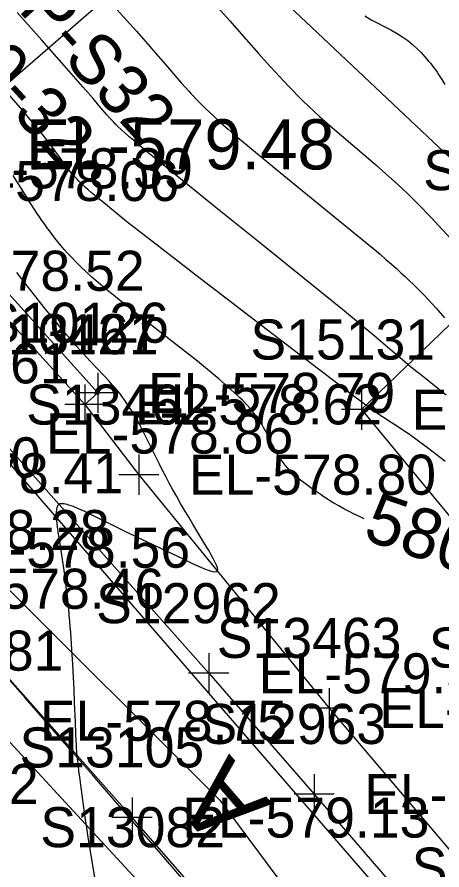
# Model space of a CAD drawing. Extents: x 1729869 to 1735532, y 648588 to 653771.
# Drawn here: x 1731271.9 to 1731314.3, y 651970.4 to 652055.5 of the extents above; entities that cross this region are included whole.
import ezdxf

# ---------------------------------------------------------------- set-up
doc = ezdxf.new("R2010")
doc.units = 0
for name, color, linetype in [('SURVEY - CENTERLINE - Preliminary', 7, 'Continuous'), ('SURVEY - CENTERLINE - Preliminary Text', 7, 'Continuous'), ('SURVEY - CONTOURS - Index with Text', 7, 'Continuous'), ('SURVEY - CONTOURS - Intermediate with optional Text', 7, 'Continuous'), ('SURVEY - CONTROL - Points - Elevations', 7, 'Continuous'), ('SURVEY - CONTROL with Text', 7, 'Continuous'), ('SURVEY - DRAINAGE - Area Shapes', 7, 'Continuous'), ('SURVEY - DRAINAGE - Area Shapes Text', 7, 'Continuous'), ('SURVEY - DRAINAGE - Storm Sewer - Points - Numbers', 7, 'Continuous'), ('SURVEY - DTM - Breaklines', 7, 'Continuous'), ('SURVEY - DTM - Breaklines - Points - Elevations', 7, 'Continuous'), ('SURVEY - DTM - Breaklines - Points - Locators', 7, 'Continuous'), ('SURVEY - DTM - Breaklines - Points - Numbers', 7, 'Continuous'), ('SURVEY - ROADSIDE BARRIERS - Points - Elevations', 7, 'Continuous'), ('SURVEY - TRANSPORTATION - Features', 7, 'Continuous'), ('SURVEY - TRANSPORTATION - Features - Points - Elevations', 7, 'Continuous'), ('SURVEY - TRANSPORTATION - Features - Points - Locators', 7, 'Continuous'), ('SURVEY - TRANSPORTATION - Features - Points - Numbers', 7, 'Continuous'), ('SURVEY - TRANSPORTATION - Roads', 7, 'Continuous'), ('SURVEY - TRANSPORTATION - Roads - Points - Elevations', 7, 'Continuous'), ('SURVEY - TRANSPORTATION - Roads - Points - Locators', 7, 'Continuous'), ('SURVEY - TRANSPORTATION - Roads - Points - Numbers', 7, 'Continuous')]:
    doc.layers.add(name, color=color, linetype=linetype)

msp = doc.modelspace()

# ---------------------------------------------------------------- linework, layer by layer
at = {"layer": 'SURVEY - CENTERLINE - Preliminary'}
msp.add_arc((1729018.342, 650008.232), 3000, 36.727042, 45.05905, dxfattribs=at)
at = {"layer": 'SURVEY - CENTERLINE - Preliminary Text'}
for p, q in [((1731256.757, 652012.701), (1731292.149, 651977.382)), ((1731292.149, 651977.382), (1731322.049, 651937.307))]:
    msp.add_line(p, q, dxfattribs=at)
at = {"layer": 'SURVEY - CONTOURS - Index with Text'}
for points in [[(1731306.619, 652055.655), (1731307.262, 652055.276), (1731307.917, 652054.924), (1731308.573, 652054.586), (1731309.22, 652054.25), (1731309.845, 652053.906), (1731310.437, 652053.54), (1731310.936, 652053.184), (1731311.403, 652052.805), (1731311.839, 652052.408), (1731312.249, 652051.995), (1731312.635, 652051.571), (1731313.001, 652051.14), (1731313.177, 652050.924), (1731313.348, 652050.706), (1731313.515, 652050.486), (1731313.679, 652050.263), (1731313.839, 652050.037), (1731313.996, 652049.808), (1731314.31, 652049.322), (1731314.611, 652048.82)], [(1731306.58, 652005.464), (1731306.117, 652005.678), (1731305.584, 652005.932), (1731305.056, 652006.193), (1731304.537, 652006.462), (1731304.029, 652006.74), (1731303.536, 652007.027), (1731303.211, 652007.227), (1731302.892, 652007.431), (1731302.579, 652007.637), (1731302.27, 652007.846), (1731301.66, 652008.268), (1731301.256, 652008.551), (1731300.856, 652008.836), (1731300.466, 652009.123), (1731300.089, 652009.416), (1731299.729, 652009.716), (1731299.391, 652010.025), (1731299.136, 652010.28), (1731298.897, 652010.541), (1731298.673, 652010.808), (1731298.463, 652011.079), (1731298.267, 652011.355), (1731298.083, 652011.634), (1731297.917, 652011.906), (1731297.761, 652012.18), (1731297.612, 652012.457), (1731297.467, 652012.737), (1731297.326, 652013.02), (1731296.943, 652013.799), (1731296.815, 652014.051), (1731296.678, 652014.309), (1731296.531, 652014.574), (1731296.37, 652014.846), (1731296.143, 652015.204), (1731295.884, 652015.578), (1731295.588, 652015.972), (1731295.248, 652016.387), (1731294.857, 652016.828), (1731294.41, 652017.296), (1731294.164, 652017.542), (1731293.901, 652017.795), (1731292.097, 652019.399), (1731289.918, 652021.182), (1731287.527, 652023.063), (1731285.086, 652024.956), (1731282.756, 652026.779), (1731280.698, 652028.448), (1731280.009, 652029.035), (1731279.38, 652029.589), (1731278.806, 652030.112), (1731278.283, 652030.608), (1731277.806, 652031.079), (1731277.37, 652031.527), (1731276.979, 652031.945), (1731276.619, 652032.347), (1731276.286, 652032.735), (1731275.975, 652033.111), (1731275.682, 652033.479), (1731275.403, 652033.841), (1731275.14, 652034.191), (1731274.885, 652034.541), (1731274.635, 652034.891), (1731274.388, 652035.244), (1731274.143, 652035.602), (1731273.898, 652035.967), (1731273.657, 652036.333), (1731273.412, 652036.709), (1731273.162, 652037.097), (1731272.907, 652037.499), (1731272.374, 652038.348), (1731271.959, 652039.016), (1731271.52, 652039.719)]]:
    msp.add_lwpolyline(points, dxfattribs=at)
at = {"layer": 'SURVEY - CONTOURS - Intermediate with optional Text'}
for points in [[(1731280.868, 652057.433), (1731283.821, 652054.117), (1731285.173, 652052.593), (1731286.009, 652051.642), (1731286.747, 652050.795), (1731288.31, 652048.983), (1731288.77, 652048.461), (1731289.012, 652048.191), (1731289.26, 652047.919), (1731289.522, 652047.637), (1731289.801, 652047.344), (1731290.1, 652047.036), (1731290.422, 652046.712), (1731290.772, 652046.369), (1731291.146, 652046.011), (1731291.552, 652045.631), (1731291.995, 652045.226), (1731292.476, 652044.794), (1731292.999, 652044.333), (1731293.567, 652043.841), (1731295.704, 652042.044), (1731298.18, 652040.014), (1731303.483, 652035.715), (1731305.98, 652033.674), (1731308.152, 652031.858), (1731308.739, 652031.354), (1731309.282, 652030.881), (1731309.783, 652030.437), (1731310.244, 652030.02), (1731310.67, 652029.628), (1731311.063, 652029.259), (1731311.498, 652028.841), (1731311.894, 652028.45), (1731312.255, 652028.084), (1731312.585, 652027.742), (1731312.89, 652027.419), (1731313.324, 652026.947), (1731313.753, 652026.469), (1731314.582, 652025.531)], [(1731291.393, 652057.137), (1731293.123, 652055.19), (1731294.796, 652053.296), (1731296.026, 652051.902), (1731296.845, 652050.982), (1731297.257, 652050.523), (1731297.676, 652050.062), (1731298.104, 652049.597), (1731298.544, 652049.126), (1731298.999, 652048.649), (1731299.462, 652048.171), (1731299.945, 652047.685), (1731300.448, 652047.189), (1731300.976, 652046.681), (1731301.53, 652046.161), (1731302.114, 652045.627), (1731303.171, 652044.688), (1731304.289, 652043.721), (1731305.435, 652042.743), (1731306.578, 652041.771), (1731307.688, 652040.819), (1731308.732, 652039.906), (1731309.326, 652039.373), (1731309.885, 652038.86), (1731310.413, 652038.365), (1731310.91, 652037.889), (1731311.379, 652037.431), (1731311.822, 652036.991), (1731312.346, 652036.46), (1731312.84, 652035.948), (1731313.313, 652035.451), (1731313.979, 652034.742), (1731315.248, 652033.374)], [(1731314.739, 652017.786), (1731313.907, 652018.482), (1731313.381, 652018.911), (1731312.891, 652019.302), (1731312.177, 652019.861), (1731311.685, 652020.245), (1731311.443, 652020.438), (1731311.199, 652020.634), (1731310.952, 652020.836), (1731310.701, 652021.047), (1731310.162, 652021.511), (1731309.175, 652022.366), (1731308.432, 652023), (1731307.548, 652023.743), (1731304.39, 652026.34), (1731300.441, 652029.539), (1731296.105, 652033.029), (1731291.786, 652036.502), (1731287.888, 652039.648), (1731284.816, 652042.159), (1731284.143, 652042.719), (1731283.564, 652043.206), (1731283.072, 652043.627), (1731282.654, 652043.993), (1731282.306, 652044.306), (1731282.017, 652044.575), (1731281.77, 652044.814), (1731281.556, 652045.031), (1731281.364, 652045.236), (1731281.177, 652045.445), (1731280.884, 652045.785), (1731280.089, 652046.72), (1731279.505, 652047.398), (1731278.758, 652048.259), (1731278.47, 652048.589), (1731276.616, 652050.699), (1731274.368, 652053.239), (1731271.923, 652055.987)], [(1731314.64, 652011.174), (1731314.198, 652011.53), (1731313.76, 652011.878), (1731313.328, 652012.216), (1731312.902, 652012.543), (1731312.507, 652012.84), (1731312.117, 652013.126), (1731311.733, 652013.403), (1731311.353, 652013.67), (1731310.977, 652013.929), (1731310.421, 652014.305), (1731309.68, 652014.795), (1731309.091, 652015.182), (1731308.674, 652015.458), (1731308.236, 652015.753), (1731307.772, 652016.07), (1731307.278, 652016.416), (1731306.748, 652016.795), (1731305.92, 652017.406), (1731304.999, 652018.101), (1731303.976, 652018.884), (1731300.182, 652021.806), (1731296.93, 652024.294), (1731293.324, 652027.046), (1731289.614, 652029.884), (1731286.051, 652032.631), (1731282.885, 652035.111), (1731280.366, 652037.147), (1731279.985, 652037.466), (1731279.634, 652037.763), (1731279.313, 652038.041), (1731279.018, 652038.301), (1731278.749, 652038.543), (1731278.504, 652038.768), (1731278.287, 652038.974), (1731278.089, 652039.167), (1731277.909, 652039.348), (1731277.745, 652039.52), (1731277.594, 652039.685), (1731277.454, 652039.843), (1731277.327, 652039.993), (1731277.206, 652040.14), (1731277.09, 652040.286), (1731276.978, 652040.433), (1731276.754, 652040.736), (1731276.139, 652041.595), (1731275.755, 652042.121), (1731275.49, 652042.476), (1731275.195, 652042.865), (1731274.866, 652043.289), (1731274.5, 652043.751), (1731274.095, 652044.253), (1731272.439, 652046.232), (1731270.447, 652048.531)], [(1731279.697, 651969.507), (1731279.481, 651970.85), (1731279.015, 651973.689), (1731278.869, 651974.619), (1731278.831, 651974.867), (1731278.749, 651975.423), (1731278.576, 651976.636), (1731278.399, 651977.928), (1731278.235, 651979.152), (1731278.162, 651979.715), (1731278.093, 651980.267), (1731278.028, 651980.803), (1731277.97, 651981.321), (1731277.921, 651981.817), (1731277.886, 651982.203), (1731277.858, 651982.575), (1731277.833, 651982.938), (1731277.812, 651983.293), (1731277.778, 651983.999), (1731277.729, 651985.203), (1731277.655, 651987.131), (1731277.597, 651988.49), (1731277.544, 651989.629), (1731277.471, 651990.987), (1731277.418, 651991.891), (1731277.349, 651992.996), (1731277.311, 651993.553), (1731277.271, 651994.113), (1731277.227, 651994.677), (1731277.181, 651995.245), (1731277.127, 651995.859), (1731277.068, 651996.479), (1731277.005, 651997.103), (1731276.936, 651997.733), (1731276.862, 651998.368), (1731276.783, 651999.007), (1731276.727, 651999.436), (1731276.668, 651999.867), (1731276.544, 652000.738), (1731276.411, 652001.619), (1731276.168, 652003.184), (1731276.056, 652003.936), (1731275.962, 652004.643), (1731275.894, 652005.287), (1731275.858, 652005.849), (1731275.855, 652006.024), (1731275.857, 652006.186), (1731275.866, 652006.335), (1731275.88, 652006.464), (1731275.902, 652006.581), (1731275.932, 652006.683), (1731275.97, 652006.772), (1731276.018, 652006.846), (1731276.077, 652006.906), (1731276.143, 652006.948), (1731276.219, 652006.978), (1731276.306, 652006.995), (1731276.402, 652007), (1731276.507, 652006.994), (1731276.622, 652006.979), (1731276.753, 652006.952), (1731276.895, 652006.916), (1731277.046, 652006.871), (1731277.499, 652006.709), (1731278.008, 652006.498), (1731278.563, 652006.248), (1731279.151, 652005.968), (1731279.761, 652005.669), (1731281.593, 652004.763), (1731282.804, 652004.171), (1731283.779, 652003.702), (1731288.572, 652001.419), (1731289.363, 652001.045), (1731289.862, 652000.814), (1731290.101, 652000.706), (1731290.333, 652000.603), (1731290.555, 652000.508), (1731290.881, 652000.377), (1731291.177, 652000.272), (1731291.434, 652000.2), (1731291.647, 652000.169), (1731291.807, 652000.185), (1731291.907, 652000.256), (1731291.941, 652000.391), (1731291.913, 652000.583), (1731291.831, 652000.827), (1731291.702, 652001.115), (1731291.534, 652001.442), (1731291.336, 652001.801), (1731291.075, 652002.252), (1731290.665, 652002.943), (1731289.472, 652004.92), (1731289.053, 652005.618), (1731288.636, 652006.323), (1731288.242, 652007.002), (1731287.856, 652007.68), (1731287.479, 652008.355), (1731287.112, 652009.027), (1731286.756, 652009.694), (1731286.413, 652010.354), (1731286.134, 652010.903), (1731285.862, 652011.448), (1731285.068, 652013.054), (1731284.805, 652013.582), (1731284.467, 652014.246), (1731284.121, 652014.902), (1731283.766, 652015.546), (1731283.399, 652016.173), (1731283.016, 652016.78), (1731282.616, 652017.363), (1731282.409, 652017.645), (1731282.196, 652017.921), (1731281.831, 652018.365), (1731281.452, 652018.8), (1731281.061, 652019.229), (1731280.66, 652019.657), (1731279.834, 652020.527), (1731279.33, 652021.065), (1731278.821, 652021.62), (1731278.308, 652022.189), (1731277.792, 652022.771), (1731277.275, 652023.365), (1731276.758, 652023.968), (1731276.255, 652024.566), (1731275.754, 652025.17), (1731275.255, 652025.78), (1731274.759, 652026.393), (1731274.265, 652027.01), (1731273.774, 652027.628), (1731273.298, 652028.232), (1731272.826, 652028.836), (1731272.358, 652029.439), (1731271.895, 652030.041)]]:
    msp.add_lwpolyline(points, dxfattribs=at)
at = {"layer": 'SURVEY - DRAINAGE - Area Shapes'}
for points in [[(1731097.142, 652171.409), (1731011.148, 652256.97), (1730865.03, 652403.158), (1730749.606, 652518.939), (1730781.764, 652550.883), (1730851.291, 652571.58), (1730949.072, 652515.98), (1730982.838, 652438.563), (1731020.351, 652368.14), (1731165.291, 652192.393), (1731281.807, 652137.032), (1731316.797, 652088.672), (1731252.279, 652032.718), (1731179.777, 652109.245)], [(1731447.67, 651794.75), (1731494.62, 651848.132), (1731494.044, 651850.166), (1731316.797, 652088.672), (1731252.279, 652032.718), (1731331.927, 651940.868), (1731377.361, 651886.729)]]:
    msp.add_lwpolyline(points, close=True, dxfattribs=at)
at = {"layer": 'SURVEY - DRAINAGE - Area Shapes Text'}
msp.add_lwpolyline([(1731252.279, 652032.718), (1731252.279, 652032.718), (1731331.927, 651940.868), (1731382.756, 651879.672), (1731447.67, 651794.75), (1731482.093, 651747.619), (1731463.009, 651708.574), (1731417.334, 651769.604), (1731372.727, 651826.43), (1731331.142, 651879.707), (1731270.184, 651948.802), (1731219.221, 652002.428), (1731149.8, 652071.308), (1731071.45, 652144.137), (1731094.843, 652173.647), (1731097.142, 652171.409), (1731179.777, 652109.245)], close=True, dxfattribs=at)
at = {"layer": 'SURVEY - DTM - Breaklines'}
for points in [[(1731035.462, 652269.556), (1731036.254, 652268.75), (1731049.78, 652255.258), (1731071.01, 652234.055), (1731092.233, 652212.831), (1731113.392, 652191.515), (1731134.61, 652170.281), (1731155.653, 652148.89), (1731176.704, 652127.515), (1731197.722, 652105.922), (1731218.638, 652084.352), (1731239.234, 652062.543), (1731259.779, 652040.444), (1731279.977, 652018.028), (1731278.681, 652016.879)], [(1731173.177, 652162.133), (1731185.96, 652157.822), (1731193.021, 652156.379), (1731200.301, 652157.188), (1731222.402, 652143.758), (1731259.134, 652109.719), (1731287.468, 652067.609), (1731323.876, 652033.257), (1731358.72, 651988.1), (1731387.259, 651947.011), (1731417.761, 651907.382), (1731444.904, 651865.257), (1731475.096, 651825.397), (1731506.912, 651797.592), (1731507.786, 651795.548)], [(1731323.876, 652033.257), (1731306.29, 652016.355), (1731329.689, 651988.026)]]:
    msp.add_lwpolyline(points, dxfattribs=at)
at = {"layer": 'SURVEY - DTM - Breaklines - Points - Locators'}
for p, q in [((1731279.977, 652020.028), (1731279.977, 652016.028)), ((1731278.681, 652018.879), (1731278.681, 652014.879)), ((1731306.29, 652018.355), (1731306.29, 652014.355)), ((1731281.977, 652018.028), (1731277.977, 652018.028)), ((1731280.681, 652016.879), (1731276.681, 652016.879)), ((1731308.29, 652016.355), (1731304.29, 652016.355))]:
    msp.add_line(p, q, dxfattribs=at)
at = {"layer": 'SURVEY - TRANSPORTATION - Features'}
msp.add_lwpolyline([(1731258.402, 652039.18), (1731278.681, 652016.879), (1731284.056, 652009.864), (1731303.088, 651986.573), (1731322.547, 651963.645), (1731341.9, 651940.638), (1731361.109, 651917.48), (1731380.078, 651894.112), (1731398.716, 651870.573), (1731417.161, 651846.862), (1731435.465, 651822.971), (1731453.412, 651798.904), (1731471.112, 651774.585), (1731488.583, 651750.084), (1731505.82, 651725.418)], dxfattribs=at)
at = {"layer": 'SURVEY - TRANSPORTATION - Features - Points - Locators'}
for p, q in [((1731278.681, 652018.879), (1731278.681, 652014.879)), ((1731280.681, 652016.879), (1731276.681, 652016.879)), ((1731284.056, 652011.864), (1731284.056, 652007.864)), ((1731286.056, 652009.864), (1731282.056, 652009.864)), ((1731303.088, 651988.573), (1731303.088, 651984.573)), ((1731305.088, 651986.573), (1731301.088, 651986.573))]:
    msp.add_line(p, q, dxfattribs=at)
at = {"layer": 'SURVEY - TRANSPORTATION - Roads'}
for points in [[(1731269.804, 652013.975), (1731291.041, 651990.04), (1731301.561, 651977.986), (1731315.932, 651961.331), (1731325.019, 651950.684), (1731350.665, 651919.992), (1731374.621, 651890.497), (1731391.943, 651868.499), (1731406.718, 651849.586), (1731426.267, 651824.251), (1731439.451, 651806.638), (1731451.385, 651790.587), (1731473.705, 651759.831), (1731495.592, 651728.764)], [(1731389.825, 651846.468), (1731363.537, 651880.004), (1731354.147, 651891.444), (1731351.684, 651894.595), (1731349.211, 651897.739), (1731327.573, 651923.962), (1731313.451, 651940.828), (1731296.544, 651960.578), (1731283.394, 651975.645), (1731259.51, 652002.579)], [(1731269.179, 651985.304), (1731285.472, 651967.686), (1731301.624, 651949.938), (1731311.008, 651939.55), (1731317.661, 651932.085), (1731326.973, 651921.632), (1731337.476, 651909.563), (1731342.707, 651903.512), (1731346.624, 651898.967), (1731350.515, 651894.4), (1731358.298, 651885.268), (1731364.785, 651877.657)]]:
    msp.add_lwpolyline(points, dxfattribs=at)
at = {"layer": 'SURVEY - TRANSPORTATION - Roads - Points - Locators'}
for p, q in [((1731291.041, 651992.04), (1731291.041, 651988.04)), ((1731293.041, 651990.04), (1731289.041, 651990.04)), ((1731301.561, 651979.986), (1731301.561, 651975.986)), ((1731283.394, 651977.645), (1731283.394, 651973.645)), ((1731303.561, 651977.986), (1731299.561, 651977.986)), ((1731285.394, 651975.645), (1731281.394, 651975.645))]:
    msp.add_line(p, q, dxfattribs=at)

# ---------------------------------------------------------------- texts
at = {"layer": 'SURVEY - CENTERLINE - Preliminary Text'}
msp.add_text('A', height=7.5, rotation=130.89305, dxfattribs=at).set_placement((1731297.438, 651977.002))
at = {"layer": 'SURVEY - CONTOURS - Index with Text'}
msp.add_text('580', height=5, rotation=340.99645, dxfattribs=at).set_placement((1731306.293, 652003.473))
at = {"layer": 'SURVEY - CONTROL - Points - Elevations'}
msp.add_text('EL-579.48', height=5, dxfattribs=at).set_placement((1731272.771, 652040.333))
msp.add_text('EL-579.48', height=5, dxfattribs=at).set_placement((1731272.771, 652040.333))
at = {"layer": 'SURVEY - CONTROL with Text'}
for s, p in [('XCP-S32', (1731265.649, 652063.09)), ('19-440-32', (1731255.813, 652062.84))]:
    msp.add_text(s, height=5, rotation=312.46606, dxfattribs=at).set_placement(p)
at = {"layer": 'SURVEY - DRAINAGE - Storm Sewer - Points - Numbers'}
msp.add_text('S352', height=4, dxfattribs=at).set_placement((1731313.018, 651990.61))
at = {"layer": 'SURVEY - DTM - Breaklines - Points - Elevations'}
for s, p in [('EL-578.39', (1731264.779, 652038.444)), ('EL-578.79', (1731284.977, 652016.028)), ('EL-578.62', (1731283.681, 652014.879)), ('EL-580.89', (1731311.29, 652014.355))]:
    msp.add_text(s, height=4, dxfattribs=at).set_placement(p)
at = {"layer": 'SURVEY - DTM - Breaklines - Points - Numbers'}
for s, p in [('S15130', (1731312.463, 652038.257)), ('S15140', (1731312.463, 652038.257)), ('S10126', (1731268.627, 652023.028)), ('S10127', (1731267.441, 652021.879)), ('S15131', (1731295.208, 652021.355))]:
    msp.add_text(s, height=4, dxfattribs=at).set_placement(p)
at = {"layer": 'SURVEY - ROADSIDE BARRIERS - Points - Elevations'}
msp.add_text('EL-577.92', height=4, dxfattribs=at).set_placement((1731249.382, 651976.991))
at = {"layer": 'SURVEY - TRANSPORTATION - Features - Points - Elevations'}
for s, p in [('EL-578.06', (1731263.402, 652037.18)), ('EL-578.62', (1731283.681, 652014.879)), ('EL-578.80', (1731289.056, 652007.864)), ('EL-579.28', (1731308.088, 651984.573))]:
    msp.add_text(s, height=4, dxfattribs=at).set_placement(p)
at = {"layer": 'SURVEY - TRANSPORTATION - Features - Points - Numbers'}
for s, p in [('S13461', (1731267.599, 652021.879)), ('S13462', (1731272.816, 652014.864)), ('S13463', (1731291.848, 651991.573)), ('S13464', (1731311.307, 651968.645))]:
    msp.add_text(s, height=4, dxfattribs=at).set_placement(p)
at = {"layer": 'SURVEY - TRANSPORTATION - Roads - Points - Elevations'}
for s, p in [('EL-578.52', (1731259.968, 652028.216)), ('EL-578.86', (1731274.804, 652011.975)), ('EL-578.10', (1731249.586, 652009.589)), ('EL-578.41', (1731257.817, 652008.007)), ('EL-578.28', (1731256.47, 652002.337)), ('EL-578.56', (1731264.51, 652000.579)), ('EL-578.46', (1731261.919, 651996.481)), ('EL-579.33', (1731296.041, 651988.04)), ('EL-578.75', (1731274.179, 651983.304)), ('EL-579.60', (1731306.561, 651975.986)), ('EL-579.13', (1731288.394, 651973.645))]:
    msp.add_text(s, height=4, dxfattribs=at).set_placement(p)
at = {"layer": 'SURVEY - TRANSPORTATION - Roads - Points - Numbers'}
for s, p in [('S12961', (1731258.722, 652018.975)), ('S12962', (1731279.801, 651995.04)), ('S13081', (1731258.097, 651990.304)), ('S12963', (1731290.321, 651982.986)), ('S13105', (1731272.154, 651980.645)), ('S13082', (1731274.232, 651972.686))]:
    msp.add_text(s, height=4, dxfattribs=at).set_placement(p)

doc.saveas('drawing.dxf')
